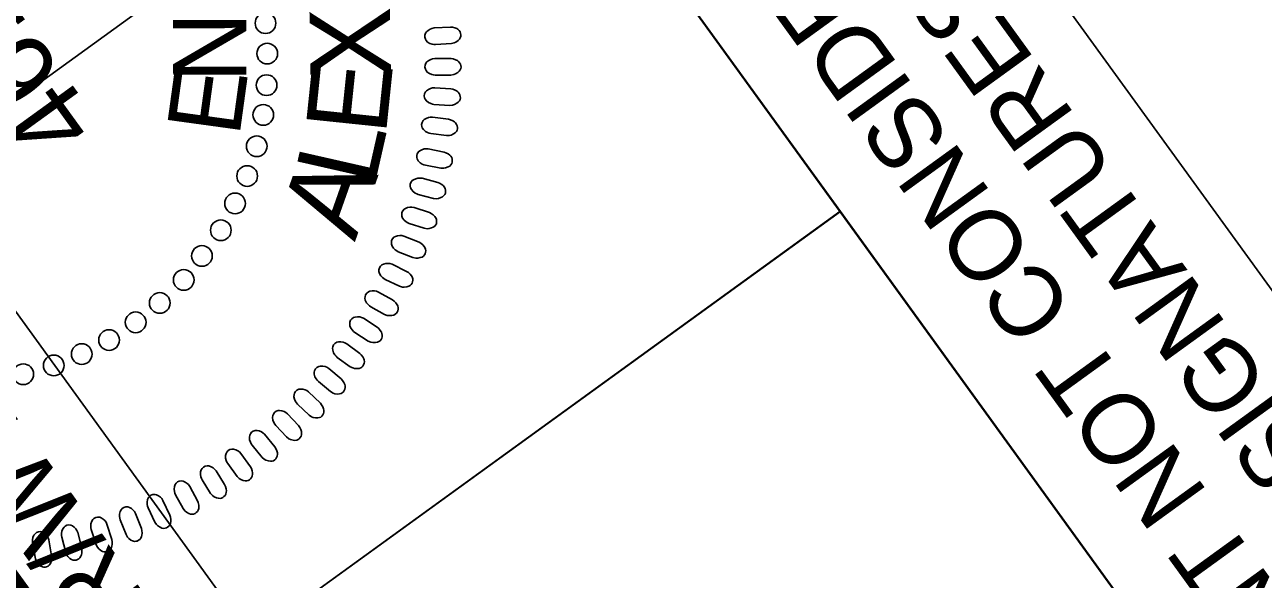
# Model space of a CAD drawing. Extents: x 474925 to 478950, y 494687 to 502905.
# Drawn here: x 475070.1 to 475166, y 502241.2 to 502284.1 of the extents above; entities that cross this region are included whole.
import ezdxf

# ---------------------------------------------------------------- set-up
doc = ezdxf.new("R2010")
doc.units = 0
for name, color, linetype in [('Sheet Layout Plan Border', 7, 'Continuous'), ('Sheet PE Seal Cell', 7, 'Continuous'), ('Sheet Plan CELL', 7, 'Continuous'), ('Sheet Plan Layout CELL', 7, 'Continuous'), ('Sheet Sticker Exception Certification CELL', 7, 'Continuous'), ('Sheet Sticker Incomplete CELL', 7, 'Continuous')]:
    doc.layers.add(name, color=color, linetype=linetype)

msp = doc.modelspace()

# ---------------------------------------------------------------- linework, layer by layer
at = {"layer": 'Sheet Layout Plan Border'}
for points in [[(476646.384, 501714.386), (476110.18, 502454.921), (476091.748, 502441.575), (476003.493, 502563.461), (475989.428, 502553.276), (475869.086, 502719.476), (475838.053, 502697.006), (475782.546, 502773.666), (475678.649, 502698.454), (475652.98, 502679.873), (475264.351, 502398.541), (475136.14, 502305.707), (475210.951, 502202.387), (475104.173, 502125.071), (475196.466, 501997.607), (475162.674, 501973.139), (475721.996, 501200.68)], [(476646.506, 501714.234), (476022.047, 502576.655), (475989.428, 502553.276), (475869.2, 502719.318), (475838.175, 502696.853), (475782.667, 502773.513), (475678.77, 502698.302), (475653.102, 502679.72), (475264.472, 502398.389), (475136.261, 502305.554), (475211.073, 502202.234), (475104.294, 502124.918), (475196.588, 501997.455), (475162.795, 501972.986), (475722.117, 501200.527)]]:
    msp.add_lwpolyline(points, close=True, dxfattribs=at)
at = {"layer": 'Sheet PE Seal Cell'}
for points in [[(475101.92, 502282.568), (475103.146, 502282.643), (475103.362, 502282.693), (475103.498, 502282.754), (475103.661, 502282.876), (475103.764, 502282.98), (475103.837, 502283.096), (475103.871, 502283.203), (475103.883, 502283.317), (475103.857, 502283.427), (475103.82, 502283.545), (475103.754, 502283.645), (475103.648, 502283.744), (475103.564, 502283.799), (475103.411, 502283.857), (475103.229, 502283.906), (475103.068, 502283.919), (475101.813, 502283.849), (475101.645, 502283.816), (475101.509, 502283.763), (475101.355, 502283.664), (475101.222, 502283.544), (475101.149, 502283.441), (475101.097, 502283.281), (475101.088, 502283.131), (475101.137, 502282.984), (475101.193, 502282.883), (475101.299, 502282.762), (475101.476, 502282.653), (475101.66, 502282.597), (475101.791, 502282.575)], [(475101.891, 502280.199), (475103.118, 502280.197), (475103.338, 502280.234), (475103.478, 502280.285), (475103.648, 502280.397), (475103.757, 502280.495), (475103.837, 502280.607), (475103.877, 502280.711), (475103.898, 502280.823), (475103.878, 502280.935), (475103.848, 502281.055), (475103.789, 502281.16), (475103.689, 502281.264), (475103.61, 502281.325), (475103.459, 502281.392), (475103.28, 502281.452), (475103.121, 502281.475), (475101.865, 502281.485), (475101.695, 502281.463), (475101.555, 502281.418), (475101.396, 502281.329), (475101.255, 502281.217), (475101.176, 502281.12), (475101.115, 502280.963), (475101.095, 502280.813), (475101.135, 502280.663), (475101.185, 502280.559), (475101.283, 502280.432), (475101.453, 502280.312), (475101.633, 502280.244), (475101.762, 502280.214)], [(475101.801, 502277.935), (475103.026, 502277.855), (475103.247, 502277.879), (475103.39, 502277.921), (475103.566, 502278.022), (475103.682, 502278.113), (475103.769, 502278.219), (475103.816, 502278.321), (475103.843, 502278.432), (475103.83, 502278.544), (475103.808, 502278.666), (475103.755, 502278.774), (475103.662, 502278.885), (475103.587, 502278.95), (475103.442, 502279.027), (475103.267, 502279.098), (475103.109, 502279.131), (475101.855, 502279.22), (475101.684, 502279.208), (475101.542, 502279.172), (475101.377, 502279.093), (475101.231, 502278.991), (475101.144, 502278.898), (475101.075, 502278.746), (475101.045, 502278.598), (475101.075, 502278.446), (475101.119, 502278.338), (475101.21, 502278.205), (475101.371, 502278.075), (475101.546, 502277.996), (475101.673, 502277.958)], [(475101.553, 502275.669), (475102.77, 502275.513), (475102.992, 502275.522), (475103.137, 502275.556), (475103.32, 502275.645), (475103.442, 502275.728), (475103.535, 502275.829), (475103.587, 502275.927), (475103.621, 502276.036), (475103.616, 502276.15), (475103.601, 502276.273), (475103.556, 502276.384), (475103.47, 502276.5), (475103.399, 502276.569), (475103.259, 502276.656), (475103.088, 502276.738), (475102.933, 502276.781), (475101.687, 502276.948), (475101.516, 502276.947), (475101.372, 502276.92), (475101.202, 502276.852), (475101.05, 502276.758), (475100.958, 502276.672), (475100.879, 502276.524), (475100.84, 502276.377), (475100.861, 502276.225), (475100.897, 502276.114), (475100.979, 502275.976), (475101.132, 502275.836), (475101.302, 502275.746), (475101.427, 502275.7)], [(475101.131, 502273.22), (475102.335, 502272.988), (475102.557, 502272.983), (475102.705, 502273.008), (475102.893, 502273.086), (475103.018, 502273.161), (475103.118, 502273.256), (475103.177, 502273.351), (475103.218, 502273.457), (475103.219, 502273.571), (475103.213, 502273.694), (475103.174, 502273.808), (475103.095, 502273.93), (475103.029, 502274.003), (475102.894, 502274.098), (475102.73, 502274.191), (475102.577, 502274.243), (475101.345, 502274.488), (475101.174, 502274.498), (475101.028, 502274.48), (475100.855, 502274.423), (475100.696, 502274.339), (475100.6, 502274.259), (475100.511, 502274.116), (475100.464, 502273.973), (475100.474, 502273.819), (475100.504, 502273.706), (475100.577, 502273.562), (475100.721, 502273.413), (475100.885, 502273.313), (475101.006, 502273.26)], [(475100.582, 502270.959), (475101.77, 502270.651), (475101.991, 502270.632), (475102.14, 502270.648), (475102.332, 502270.714), (475102.463, 502270.78), (475102.568, 502270.869), (475102.633, 502270.96), (475102.68, 502271.064), (475102.689, 502271.177), (475102.69, 502271.301), (475102.659, 502271.417), (475102.588, 502271.543), (475102.526, 502271.621), (475102.397, 502271.724), (475102.239, 502271.826), (475102.09, 502271.889), (475100.875, 502272.211), (475100.706, 502272.232), (475100.559, 502272.222), (475100.383, 502272.176), (475100.219, 502272.103), (475100.117, 502272.029), (475100.02, 502271.892), (475099.963, 502271.752), (475099.965, 502271.597), (475099.987, 502271.483), (475100.051, 502271.335), (475100.185, 502271.177), (475100.343, 502271.066), (475100.461, 502271.005)], [(475099.881, 502268.719), (475101.048, 502268.337), (475101.267, 502268.305), (475101.417, 502268.31), (475101.613, 502268.365), (475101.747, 502268.423), (475101.858, 502268.505), (475101.928, 502268.591), (475101.983, 502268.692), (475101.998, 502268.804), (475102.007, 502268.928), (475101.983, 502269.046), (475101.92, 502269.176), (475101.863, 502269.258), (475101.742, 502269.368), (475101.59, 502269.481), (475101.445, 502269.552), (475100.253, 502269.949), (475100.085, 502269.981), (475099.938, 502269.981), (475099.759, 502269.946), (475099.591, 502269.883), (475099.485, 502269.816), (475099.379, 502269.685), (475099.314, 502269.549), (475099.306, 502269.394), (475099.32, 502269.279), (475099.375, 502269.127), (475099.499, 502268.962), (475099.649, 502268.841), (475099.763, 502268.773)], [(475099.03, 502266.526), (475100.171, 502266.072), (475100.388, 502266.026), (475100.537, 502266.023), (475100.736, 502266.064), (475100.874, 502266.114), (475100.99, 502266.189), (475101.065, 502266.271), (475101.125, 502266.368), (475101.148, 502266.48), (475101.164, 502266.602), (475101.148, 502266.721), (475101.094, 502266.855), (475101.042, 502266.94), (475100.928, 502267.058), (475100.783, 502267.18), (475100.643, 502267.26), (475099.478, 502267.732), (475099.313, 502267.774), (475099.166, 502267.783), (475098.985, 502267.759), (475098.814, 502267.707), (475098.703, 502267.646), (475098.59, 502267.522), (475098.516, 502267.391), (475098.498, 502267.237), (475098.506, 502267.122), (475098.551, 502266.966), (475098.664, 502266.793), (475098.807, 502266.663), (475098.916, 502266.588)], [(475098.028, 502264.373), (475099.138, 502263.848), (475099.351, 502263.788), (475099.5, 502263.776), (475099.701, 502263.804), (475099.843, 502263.846), (475099.962, 502263.913), (475100.043, 502263.99), (475100.109, 502264.084), (475100.138, 502264.193), (475100.162, 502264.315), (475100.153, 502264.434), (475100.108, 502264.572), (475100.061, 502264.66), (475099.955, 502264.784), (475099.818, 502264.915), (475099.684, 502265.004), (475098.551, 502265.548), (475098.388, 502265.6), (475098.242, 502265.619), (475098.06, 502265.606), (475097.886, 502265.565), (475097.772, 502265.511), (475097.651, 502265.395), (475097.569, 502265.267), (475097.541, 502265.116), (475097.541, 502265), (475097.577, 502264.842), (475097.68, 502264.662), (475097.813, 502264.524), (475097.917, 502264.442)], [(475096.902, 502262.264), (475097.976, 502261.671), (475098.186, 502261.598), (475098.334, 502261.576), (475098.536, 502261.593), (475098.679, 502261.624), (475098.804, 502261.684), (475098.889, 502261.756), (475098.961, 502261.845), (475098.997, 502261.953), (475099.029, 502262.072), (475099.027, 502262.192), (475098.99, 502262.332), (475098.95, 502262.423), (475098.851, 502262.554), (475098.722, 502262.693), (475098.594, 502262.79), (475097.498, 502263.405), (475097.338, 502263.467), (475097.194, 502263.495), (475097.012, 502263.494), (475096.835, 502263.464), (475096.718, 502263.417), (475096.589, 502263.308), (475096.5, 502263.186), (475096.463, 502263.037), (475096.456, 502262.92), (475096.481, 502262.761), (475096.572, 502262.575), (475096.697, 502262.429), (475096.796, 502262.34)], [(475095.681, 502260.27), (475096.715, 502259.61), (475096.921, 502259.523), (475097.066, 502259.492), (475097.269, 502259.496), (475097.414, 502259.519), (475097.542, 502259.571), (475097.631, 502259.637), (475097.709, 502259.721), (475097.752, 502259.826), (475097.791, 502259.943), (475097.797, 502260.063), (475097.769, 502260.205), (475097.734, 502260.299), (475097.644, 502260.436), (475097.524, 502260.582), (475097.402, 502260.688), (475096.347, 502261.369), (475096.191, 502261.442), (475096.05, 502261.479), (475095.867, 502261.489), (475095.689, 502261.469), (475095.569, 502261.43), (475095.434, 502261.33), (475095.337, 502261.214), (475095.291, 502261.068), (475095.277, 502260.952), (475095.292, 502260.791), (475095.371, 502260.6), (475095.486, 502260.446), (475095.58, 502260.352)], [(475094.314, 502258.343), (475095.305, 502257.62), (475095.504, 502257.521), (475095.647, 502257.48), (475095.851, 502257.471), (475095.997, 502257.485), (475096.127, 502257.529), (475096.221, 502257.59), (475096.303, 502257.668), (475096.353, 502257.771), (475096.399, 502257.885), (475096.413, 502258.005), (475096.393, 502258.148), (475096.365, 502258.243), (475096.283, 502258.386), (475096.173, 502258.54), (475096.058, 502258.652), (475095.047, 502259.399), (475094.897, 502259.48), (475094.757, 502259.527), (475094.576, 502259.548), (475094.397, 502259.54), (475094.275, 502259.509), (475094.135, 502259.417), (475094.03, 502259.308), (475093.974, 502259.164), (475093.953, 502259.05), (475093.958, 502258.889), (475094.025, 502258.692), (475094.13, 502258.532), (475094.218, 502258.431)], [(475092.847, 502256.474), (475093.791, 502255.69), (475093.984, 502255.579), (475094.124, 502255.529), (475094.326, 502255.507), (475094.473, 502255.512), (475094.606, 502255.548), (475094.703, 502255.603), (475094.791, 502255.676), (475094.846, 502255.775), (475094.9, 502255.886), (475094.921, 502256.004), (475094.911, 502256.149), (475094.888, 502256.246), (475094.816, 502256.393), (475094.716, 502256.554), (475094.608, 502256.673), (475093.646, 502257.482), (475093.501, 502257.573), (475093.365, 502257.627), (475093.185, 502257.66), (475093.006, 502257.664), (475092.883, 502257.64), (475092.736, 502257.557), (475092.625, 502257.455), (475092.56, 502257.314), (475092.532, 502257.202), (475092.527, 502257.04), (475092.581, 502256.841), (475092.676, 502256.673), (475092.757, 502256.568)], [(475091.232, 502254.712), (475092.125, 502253.871), (475092.31, 502253.747), (475092.447, 502253.689), (475092.648, 502253.655), (475092.795, 502253.65), (475092.929, 502253.677), (475093.03, 502253.726), (475093.122, 502253.794), (475093.184, 502253.889), (475093.244, 502253.997), (475093.273, 502254.114), (475093.271, 502254.259), (475093.255, 502254.357), (475093.192, 502254.509), (475093.102, 502254.675), (475093.002, 502254.801), (475092.092, 502255.668), (475091.953, 502255.768), (475091.821, 502255.831), (475091.644, 502255.875), (475091.465, 502255.89), (475091.34, 502255.874), (475091.189, 502255.801), (475091.072, 502255.705), (475090.999, 502255.569), (475090.963, 502255.459), (475090.948, 502255.298), (475090.99, 502255.095), (475091.074, 502254.922), (475091.148, 502254.812)], [(475089.544, 502253.078), (475090.382, 502252.182), (475090.559, 502252.048), (475090.693, 502251.981), (475090.891, 502251.934), (475091.037, 502251.92), (475091.173, 502251.939), (475091.276, 502251.981), (475091.373, 502252.044), (475091.44, 502252.135), (475091.507, 502252.238), (475091.543, 502252.353), (475091.551, 502252.498), (475091.54, 502252.597), (475091.488, 502252.752), (475091.408, 502252.924), (475091.316, 502253.056), (475090.463, 502253.979), (475090.331, 502254.087), (475090.202, 502254.158), (475090.028, 502254.214), (475089.851, 502254.239), (475089.725, 502254.231), (475089.57, 502254.167), (475089.447, 502254.08), (475089.365, 502253.949), (475089.323, 502253.84), (475089.297, 502253.681), (475089.326, 502253.476), (475089.4, 502253.299), (475089.467, 502253.183)], [(475087.712, 502251.549), (475088.492, 502250.602), (475088.661, 502250.456), (475088.789, 502250.381), (475088.984, 502250.322), (475089.129, 502250.299), (475089.266, 502250.309), (475089.372, 502250.345), (475089.472, 502250.401), (475089.545, 502250.487), (475089.618, 502250.587), (475089.662, 502250.699), (475089.678, 502250.843), (475089.674, 502250.942), (475089.631, 502251.1), (475089.563, 502251.277), (475089.479, 502251.414), (475088.685, 502252.389), (475088.56, 502252.506), (475088.437, 502252.584), (475088.266, 502252.651), (475088.091, 502252.687), (475087.965, 502252.687), (475087.806, 502252.634), (475087.678, 502252.554), (475087.588, 502252.428), (475087.538, 502252.323), (475087.504, 502252.165), (475087.519, 502251.959), (475087.582, 502251.777), (475087.641, 502251.658)], [(475085.833, 502250.124), (475086.553, 502249.13), (475086.712, 502248.974), (475086.835, 502248.891), (475087.026, 502248.82), (475087.169, 502248.787), (475087.307, 502248.789), (475087.414, 502248.818), (475087.517, 502248.868), (475087.596, 502248.949), (475087.676, 502249.044), (475087.725, 502249.153), (475087.752, 502249.296), (475087.753, 502249.395), (475087.72, 502249.556), (475087.663, 502249.737), (475087.588, 502249.879), (475086.857, 502250.902), (475086.74, 502251.026), (475086.621, 502251.112), (475086.455, 502251.189), (475086.283, 502251.236), (475086.157, 502251.244), (475085.995, 502251.201), (475085.862, 502251.129), (475085.765, 502251.009), (475085.709, 502250.907), (475085.664, 502250.752), (475085.667, 502250.545), (475085.718, 502250.36), (475085.769, 502250.237)], [(475083.853, 502248.85), (475084.508, 502247.813), (475084.657, 502247.647), (475084.776, 502247.557), (475084.961, 502247.474), (475085.102, 502247.432), (475085.239, 502247.425), (475085.349, 502247.447), (475085.455, 502247.491), (475085.538, 502247.568), (475085.624, 502247.657), (475085.68, 502247.763), (475085.715, 502247.903), (475085.723, 502248.003), (475085.701, 502248.165), (475085.655, 502248.349), (475085.589, 502248.496), (475084.924, 502249.562), (475084.814, 502249.694), (475084.702, 502249.787), (475084.54, 502249.874), (475084.372, 502249.933), (475084.247, 502249.948), (475084.082, 502249.915), (475083.945, 502249.852), (475083.84, 502249.738), (475083.778, 502249.64), (475083.724, 502249.488), (475083.713, 502249.281), (475083.752, 502249.093), (475083.797, 502248.968)], [(475081.786, 502247.708), (475082.376, 502246.631), (475082.513, 502246.457), (475082.626, 502246.359), (475082.806, 502246.264), (475082.944, 502246.214), (475083.081, 502246.198), (475083.191, 502246.214), (475083.3, 502246.25), (475083.388, 502246.321), (475083.479, 502246.405), (475083.542, 502246.508), (475083.586, 502246.646), (475083.6, 502246.744), (475083.587, 502246.908), (475083.553, 502247.094), (475083.497, 502247.245), (475082.9, 502248.351), (475082.798, 502248.489), (475082.692, 502248.589), (475082.538, 502248.686), (475082.372, 502248.755), (475082.248, 502248.778), (475082.082, 502248.756), (475081.94, 502248.701), (475081.829, 502248.595), (475081.761, 502248.5), (475081.697, 502248.352), (475081.674, 502248.146), (475081.701, 502247.956), (475081.737, 502247.828)], [(475079.665, 502246.691), (475080.185, 502245.58), (475080.312, 502245.397), (475080.418, 502245.292), (475080.593, 502245.186), (475080.727, 502245.128), (475080.863, 502245.104), (475080.974, 502245.112), (475081.084, 502245.141), (475081.177, 502245.207), (475081.272, 502245.285), (475081.342, 502245.383), (475081.394, 502245.518), (475081.415, 502245.615), (475081.413, 502245.78), (475081.39, 502245.968), (475081.343, 502246.121), (475080.817, 502247.263), (475080.725, 502247.407), (475080.624, 502247.514), (475080.476, 502247.62), (475080.315, 502247.7), (475080.193, 502247.731), (475080.026, 502247.718), (475079.882, 502247.673), (475079.763, 502247.573), (475079.69, 502247.484), (475079.617, 502247.34), (475079.58, 502247.136), (475079.596, 502246.944), (475079.624, 502246.814)], [(475077.506, 502245.758), (475077.956, 502244.617), (475078.071, 502244.427), (475078.17, 502244.315), (475078.337, 502244.199), (475078.467, 502244.132), (475078.601, 502244.099), (475078.713, 502244.101), (475078.825, 502244.123), (475078.922, 502244.182), (475079.022, 502244.254), (475079.098, 502244.348), (475079.158, 502244.479), (475079.185, 502244.575), (475079.193, 502244.74), (475079.182, 502244.928), (475079.145, 502245.085), (475078.692, 502246.257), (475078.609, 502246.407), (475078.516, 502246.52), (475078.374, 502246.635), (475078.219, 502246.724), (475078.099, 502246.763), (475077.93, 502246.761), (475077.784, 502246.725), (475077.66, 502246.633), (475077.581, 502246.548), (475077.499, 502246.409), (475077.45, 502246.208), (475077.453, 502246.016), (475077.473, 502245.884)], [(475075.266, 502245.006), (475075.643, 502243.839), (475075.746, 502243.642), (475075.838, 502243.524), (475075.997, 502243.397), (475076.124, 502243.323), (475076.255, 502243.281), (475076.366, 502243.276), (475076.479, 502243.292), (475076.58, 502243.345), (475076.685, 502243.41), (475076.765, 502243.499), (475076.835, 502243.626), (475076.867, 502243.721), (475076.885, 502243.884), (475076.887, 502244.072), (475076.859, 502244.231), (475076.481, 502245.43), (475076.407, 502245.584), (475076.321, 502245.703), (475076.187, 502245.827), (475076.037, 502245.925), (475075.92, 502245.972), (475075.753, 502245.981), (475075.604, 502245.954), (475075.474, 502245.869), (475075.391, 502245.79), (475075.299, 502245.656), (475075.238, 502245.458), (475075.229, 502245.266), (475075.24, 502245.134)], [(475070.712, 502243.95), (475070.94, 502242.744), (475071.017, 502242.535), (475071.094, 502242.408), (475071.236, 502242.262), (475071.352, 502242.172), (475071.477, 502242.115), (475071.587, 502242.095), (475071.701, 502242.096), (475071.807, 502242.137), (475071.919, 502242.189), (475072.011, 502242.266), (475072.095, 502242.384), (475072.139, 502242.473), (475072.178, 502242.633), (475072.203, 502242.821), (475072.196, 502242.981), (475071.97, 502244.218), (475071.916, 502244.38), (475071.846, 502244.508), (475071.729, 502244.649), (475071.592, 502244.765), (475071.483, 502244.826), (475071.317, 502244.856), (475071.166, 502244.847), (475071.027, 502244.78), (475070.933, 502244.712), (475070.827, 502244.59), (475070.741, 502244.402), (475070.708, 502244.213), (475070.703, 502244.079)], [(475072.979, 502244.431), (475073.282, 502243.243), (475073.373, 502243.04), (475073.457, 502242.917), (475073.608, 502242.78), (475073.729, 502242.698), (475073.857, 502242.649), (475073.969, 502242.636), (475074.083, 502242.644), (475074.186, 502242.691), (475074.295, 502242.75), (475074.381, 502242.833), (475074.458, 502242.955), (475074.497, 502243.048), (475074.525, 502243.21), (475074.538, 502243.398), (475074.521, 502243.558), (475074.218, 502244.778), (475074.154, 502244.936), (475074.076, 502245.061), (475073.95, 502245.193), (475073.807, 502245.301), (475073.693, 502245.354), (475073.526, 502245.374), (475073.377, 502245.356), (475073.242, 502245.281), (475073.152, 502245.206), (475073.053, 502245.078), (475072.98, 502244.885), (475072.959, 502244.694), (475072.962, 502244.56)]]:
    msp.add_lwpolyline(points, close=True, dxfattribs=at)
for centre in [(475088.753, 502284.222), (475088.887, 502281.862), (475088.836, 502279.418), (475088.581, 502277.12), (475088.077, 502274.691), (475087.335, 502272.386), (475086.398, 502270.263), (475085.294, 502268.187), (475083.834, 502266.196), (475082.423, 502264.34), (475080.567, 502262.555), (475078.701, 502261.057), (475076.64, 502259.684), (475074.526, 502258.597), (475072.359, 502257.717), (475069.997, 502257.04)]:
    msp.add_circle(centre, 0.801, dxfattribs=at)
at = {"layer": 'Sheet Plan CELL'}
msp.add_line((475042.137, 502203.66), (475133.22, 502269.627), dxfattribs=at)
for points in [[(476683.281, 501663.491), (475832.823, 501047.663), (475070.379, 502100.597), (475191.917, 502188.605), (475074.61, 502350.635), (475803.528, 502878.428)], [(475042.137, 502203.66), (474983.486, 502284.639), (475074.61, 502350.635), (475133.268, 502269.646)], [(475100.814, 502122.623), (475042.137, 502203.66), (475133.268, 502269.646), (475191.917, 502188.605)]]:
    msp.add_lwpolyline(points, close=True, dxfattribs=at)
at = {"layer": 'Sheet Plan Layout CELL'}
msp.add_lwpolyline([(475297.285, 502147.842), (475156.955, 502341.646), (474985.643, 502217.634), (475125.987, 502023.809)], close=True, dxfattribs=at)
at = {"layer": 'Sheet Sticker Exception Certification CELL'}
for p, q in [((475093.634, 502364.41), (475210.951, 502202.387)), ((475093.634, 502364.41), (475210.951, 502202.387)), ((475191.917, 502188.605), (475074.6, 502350.628)), ((475191.917, 502188.605), (475074.6, 502350.628))]:
    msp.add_line(p, q, dxfattribs=at)
at = {"layer": 'Sheet Sticker Incomplete CELL'}
msp.add_lwpolyline([(475130.803, 502177.117), (475111.769, 502163.335), (475025.557, 502282.4), (475044.591, 502296.182)], close=True, dxfattribs=at)

# ---------------------------------------------------------------- texts
at = {"layer": 'Sheet PE Seal Cell'}
for s, height, rotation, p in [('46155', 6.2363, 125.88878, (475075.939, 502276.488)), ('X', 6.236, 90.90186, (475098.477, 502279.967)), ('N', 5.669, 90.1128, (475087.275, 502279.612)), ('E', 6.236, 84.0562, (475098.064, 502275.468)), ('E', 5.669, 82.17301, (475086.72, 502275.34)), ('L', 6.236, 77.21054, (475097.159, 502271.464)), ('A', 6.236, 70.59087, (475095.668, 502267.248))]:
    msp.add_text(s, height=height, rotation=rotation, dxfattribs=at).set_placement(p)
at = {"layer": 'Sheet Sticker Exception Certification CELL'}
for s, p in [('UNLESS ALL SIGNATURES COMPLETED', (475198.041, 502212.792)), ('UNLESS ALL SIGNATURES COMPLETED', (475198.041, 502212.792)), ('DOCUMENT NOT CONSIDERED FINAL', (475187.939, 502211.739)), ('DOCUMENT NOT CONSIDERED FINAL', (475187.939, 502211.739))]:
    msp.add_text(s, height=5.5, rotation=125.90742, dxfattribs=at).set_placement(p)
at = {"layer": 'Sheet Sticker Incomplete CELL'}
for s, height, p in [('INCOMPLETE PLANS', 11.52, (475116.078, 502177.504)), ('DO NOT USE FOR R/W ACQUISITION', 5.76, (475119.801, 502184.213))]:
    msp.add_text(s, height=height, rotation=125.90742, dxfattribs=at).set_placement(p)

doc.saveas('drawing.dxf')
